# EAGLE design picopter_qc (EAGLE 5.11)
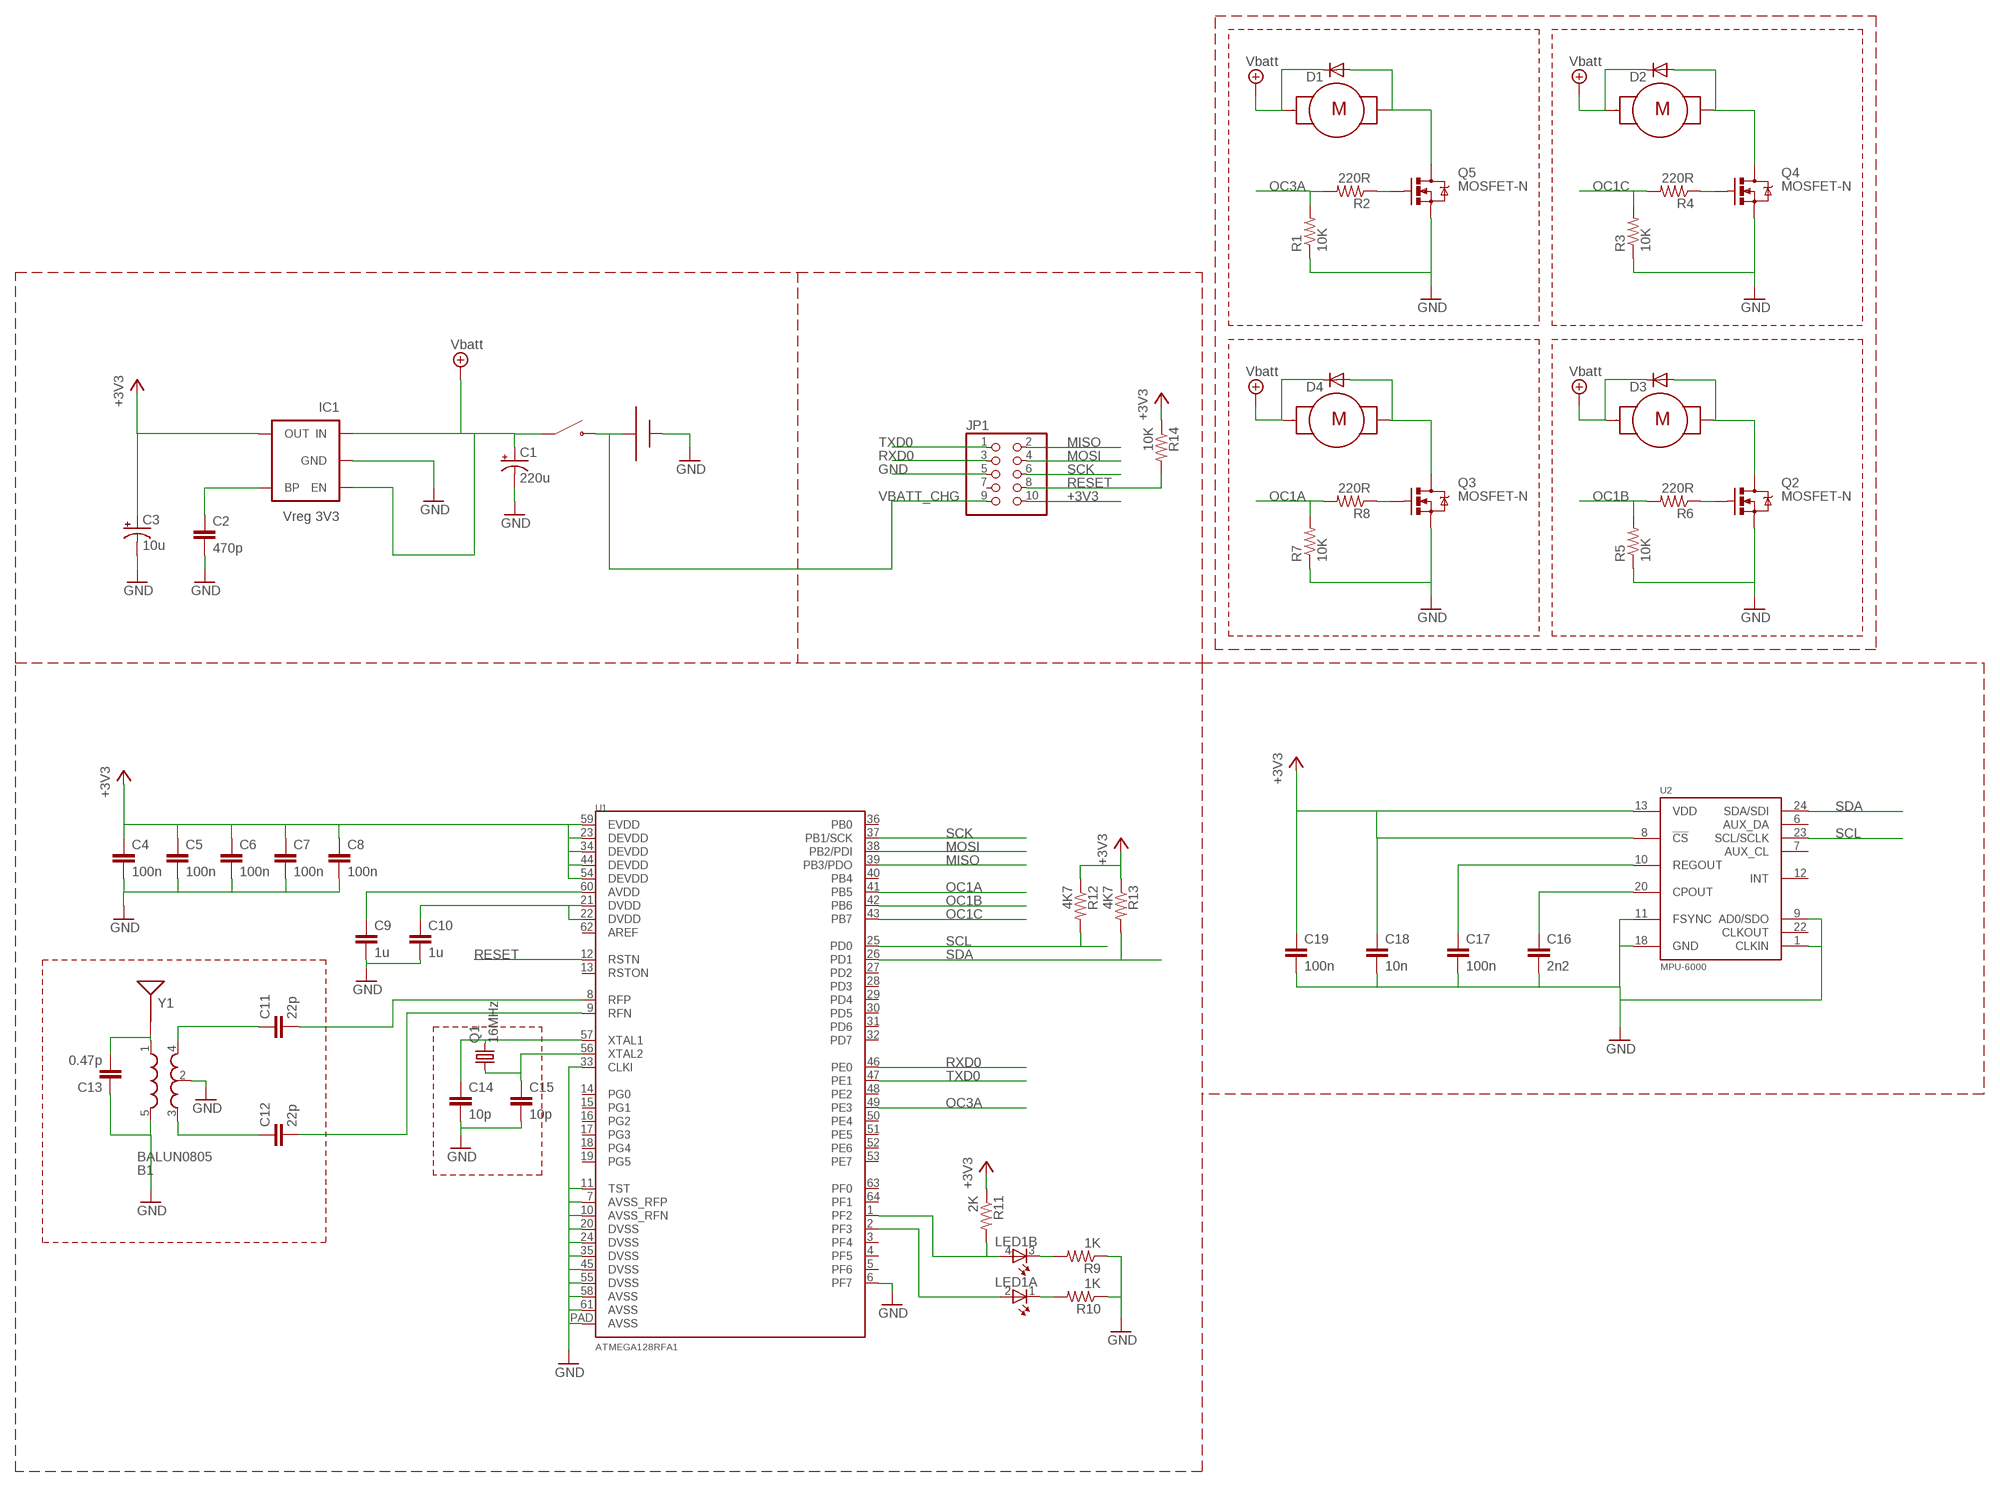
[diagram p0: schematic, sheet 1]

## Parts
B1  BALUN0805  [BALUN]
BATT1  BATT-CONNJST-PH-VERT  [JST-PH-2-VERT]
C1  220u  CPOL-USSMCB  [SMC_B]
C2  470p  C-EUC0603  [C0603]
C3  10u  CPOL-USSMCB  [SMC_B]
C4  100n  C-EUC0603  [C0603]
C5  100n  C-EUC0603  [C0603]
C6  100n  C-EUC0603  [C0603]
C7  100n  C-EUC0603  [C0603]
C8  100n  C-EUC0603  [C0603]
C9  1u  C-EUC0603  [C0603]
C10  1u  C-EUC0603  [C0603]
C11  22p  C-EUC0603  [C0603]
C12  22p  C-EUC0603  [C0603]
C13  0.47p  C-EUC0603  [C0603]
C14  10p  C-EUC0603  [C0603]
C15  10p  C-EUC0603  [C0603]
C16  2n2  C-EUC0603  [C0603]
C17  100n  C-EUC0603  [C0603]
C18  10n  C-EUC0603  [C0603]
C19  100n  C-EUC0603  [C0603]
D1  DIODE-MINIMELF  [MINIMELF]
D2  DIODE-MINIMELF  [MINIMELF]
D3  DIODE-MINIMELF  [MINIMELF]
D4  DIODE-MINIMELF  [MINIMELF]
IC1  Vreg 3V3  V_REG_LDOSMD  [SOT23-5]
JP1  PINHD-2X5EDGE  [2X5-EDGE]
LED1  TOPLED-2-CUSTOM  [TOPLED2CUSTOM]
M1  MOTORARM-CORNER  [MOTOR-CORNER-2]
M2  MOTORARM-CORNER  [MOTOR-CORNER-2]
M3  MOTORARM-CORNER  [MOTOR-CORNER-2]
M4  MOTORARM-CORNER  [MOTOR-CORNER-2]
Q1  16MHz  CRYSTALCTS406  [CTS406]
Q2  MOSFET-N  MOSFET-NCHANNELSMD  [SOT23-3]
Q3  MOSFET-N  MOSFET-NCHANNELSMD  [SOT23-3]
Q4  MOSFET-N  MOSFET-NCHANNELSMD  [SOT23-3]
Q5  MOSFET-N  MOSFET-NCHANNELSMD  [SOT23-3]
R1  10K  R-US_R0603  [R0603]
R2  220R  R-US_R0603  [R0603]
R3  10K  R-US_R0603  [R0603]
R4  220R  R-US_R0603  [R0603]
R5  10K  R-US_R0603  [R0603]
R6  220R  R-US_R0603  [R0603]
R7  10K  R-US_R0603  [R0603]
R8  220R  R-US_R0603  [R0603]
R9  1K  R-US_R0603  [R0603]
R10  1K  R-US_R0603  [R0603]
R11  2K  R-US_R0603  [R0603]
R12  4K7  R-US_R0603  [R0603]
R13  4K7  R-US_R0603  [R0603]
R14  10K  R-US_R0603  [R0603]
S2  SWITCH-PWR-SIMPLE  [SWITCH-PWR]
U1  ATMEGA128RFA1  [QFN-64]
U2  MPU-6000  [QFN-24]
Y1  ANTENNA2SMD5  [ANTENNA-CHIP5]

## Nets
+3V3: C3.+ C4.1 C5.1 C6.1 C7.1 C8.1 C18.1 C19.1 IC1.5(OUT) JP1.10 R11.1 R12.1 R13.1 R14.1 U1.23(DEVDD) U1.34(DEVDD) U1.44(DEVDD) U1.54(DEVDD) U1.59(EVDD) U2.8(!CS) U2.13(VDD)
GND: B1.2(GND) B1.5(GND) BATT1.N C1.- C2.2 C3.- C4.2 C5.2 C6.2 C7.2 C8.2 C9.2 C10.2 C13.1 C14.2 C15.2 C16.2 C17.2 C18.2 C19.2 IC1.2(GND) JP1.5 Q2.2(S) Q3.2(S) Q4.2(S) Q5.2(S) R1.1 R3.1 R5.1 R7.1 R9.1 R10.1 U1.6(PF7) U1.7(AVSS_RFP) U1.10(AVSS_RFN) U1.11(TST) U1.20(DVSS) U1.24(DVSS) U1.33(CLKI) U1.35(DVSS) U1.45(DVSS) U1.55(DVSS) U1.58(AVSS) U1.61(AVSS) U1.PAD(AVSS) U2.1(CLKIN) U2.9(AD0/SDO) U2.11(FSYNC) U2.18(GND)
MISO: JP1.2 U1.39(PB3/PDO)
MOSI: JP1.4 U1.38(PB2/PDI)
MS1: B1.1(IN) C13.2 Y1.FEED(SIGNAL)
N$1: C2.1 IC1.4(BP)
N$2: LED1.4(B:A) R11.2 U1.1(PF2)
N$3: C11.2 U1.8(RFP)
N$4: C10.1 U1.21(DVDD) U1.22(DVDD)
N$5: C9.1 U1.60(AVDD)
N$6: B1.3(OUT1) C12.1
N$7: B1.4(OUT2) C11.1
N$8: C12.2 U1.9(RFN)
N$9: C14.1 Q1.3 U1.57(XTAL1)
N$10: C15.1 Q1.1 U1.56(XTAL2)
N$11: LED1.3(B:C) R9.2
N$12: LED1.1(A:C) R10.2
N$13: LED1.2(A:A) U1.2(PF3)
N$16: C16.1 U2.20(CPOUT)
N$17: C17.1 U2.10(REGOUT)
N$18: D4.A M2.B@1 Q3.3(D)
N$19: D2.A M3.B@1 Q4.3(D)
N$20: D1.A M4.B@1 Q5.3(D)
N$21: D3.A M1.B@1 Q2.3(D)
N$45: Q5.1(G) R2.1
N$46: Q4.1(G) R4.1
N$47: Q2.1(G) R6.1
N$48: Q3.1(G) R8.1
OC1A: R7.2 R8.2 U1.41(PB5)
OC1B: R5.2 R6.2 U1.42(PB6)
OC1C: R3.2 R4.2 U1.43(PB7)
OC3A: R1.2 R2.2 U1.49(PE3)
RESET: JP1.8 R14.2 U1.12(RSTN)
RXD0: JP1.3 U1.46(PE0)
SCK: JP1.6 U1.37(PB1/SCK)
SCL: R12.2 U1.25(PD0) U2.23(SCL/SCLK)
SDA: R13.2 U1.26(PD1) U2.24(SDA/SDI)
TXD0: JP1.1 U1.47(PE1)
VBATT: C1.+ D1.C D2.C D3.C D4.C IC1.1(IN) IC1.3(EN) M1.A@1 M2.A@1 M3.A@1 M4.A@1 S2.P$1 ; supply symbol labelled Vbatt
VBATT_CHG: BATT1.P JP1.9 S2.P$2
Unconnected: JP1.7 U1.3(PF4) U1.4(PF5) U1.5(PF6) U1.13(RSTON) U1.14(PG0) U1.15(PG1) U1.16(PG2) U1.17(PG3) U1.18(PG4) U1.19(PG5) U1.27(PD2) U1.28(PD3) U1.29(PD4) U1.30(PD5) U1.31(PD6) U1.32(PD7) U1.36(PB0) U1.40(PB4) U1.48(PE2) U1.50(PE4) U1.51(PE5) U1.52(PE6) U1.53(PE7) U1.62(AREF) U1.63(PF0) U1.64(PF1) U2.6(AUX_DA) U2.7(AUX_CL) U2.12(INT) U2.22(CLKOUT)

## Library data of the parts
B1 = palmquad_alpha:BALUN
BATT1 = palmquad_alpha:BATT-CONN
C1 C3 = rcl:CPOL-US: POLARIZED CAPACITOR, American symbol
C2 C4-C19 = rcl:C-EU: CAPACITOR, European symbol
D1-D4 = palmquad_alpha:DIODE-: DIODE
IC1 = palmquad_alpha:V_REG_LDO: Voltage Regulator LDO Standard 150mA LDO voltage regulator in SOT-23 layout. Micrel part MIC5205. BP (by-pass) pin is used to lower output noise with 470pF cap.
JP1 = palmquad_alpha:PINHD-2X5: PIN HEADER
LED1 = palmquad_alpha:TOPLED-2-: Multi TOPLED® (two color) LG T672, LP T672 LSY T67B LSW T67C LSY T675 LSY T676 LSG T677 LSG T770 Source: http://www.osram.convergy.de/
M1-M4 = palmquad_alpha:MOTOR
Q1 = palmquad_alpha:CRYSTAL: CRYSTAL; OC_FARNELL: unknown; OC_NEWARK: unknown
Q2-Q5 = palmquad_alpha:MOSFET-NCHANNEL
R1-R14 = rcl:R-US_: RESISTOR, American symbol
S2 = palmquad_alpha:SWITCH-PWR
U1 = palmquad_alpha:ATMEGA128RFA1
U2 = palmquad_alpha:MPU-6000: ITG-3200 3-axis gyro, digital output, qfn24 package
Y1 = palmquad_alpha:ANTENNA2: Antenna

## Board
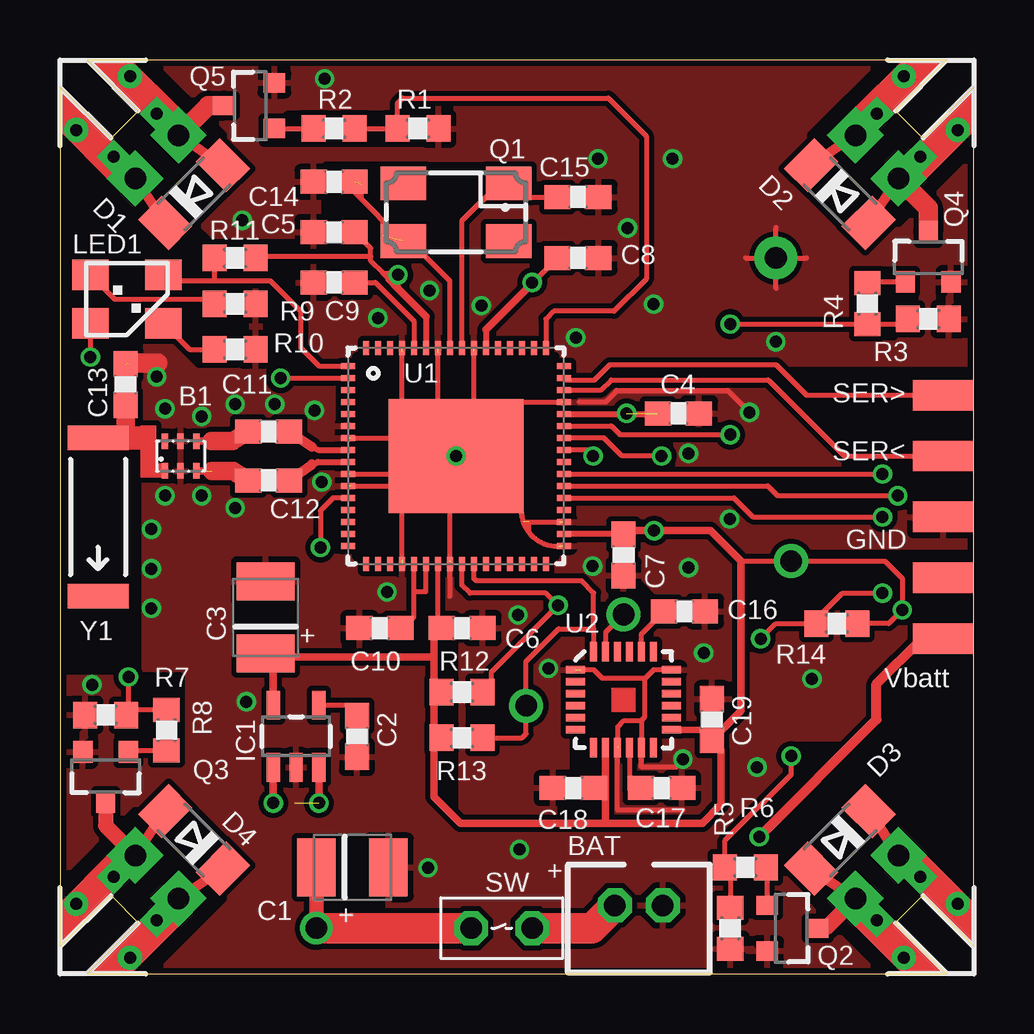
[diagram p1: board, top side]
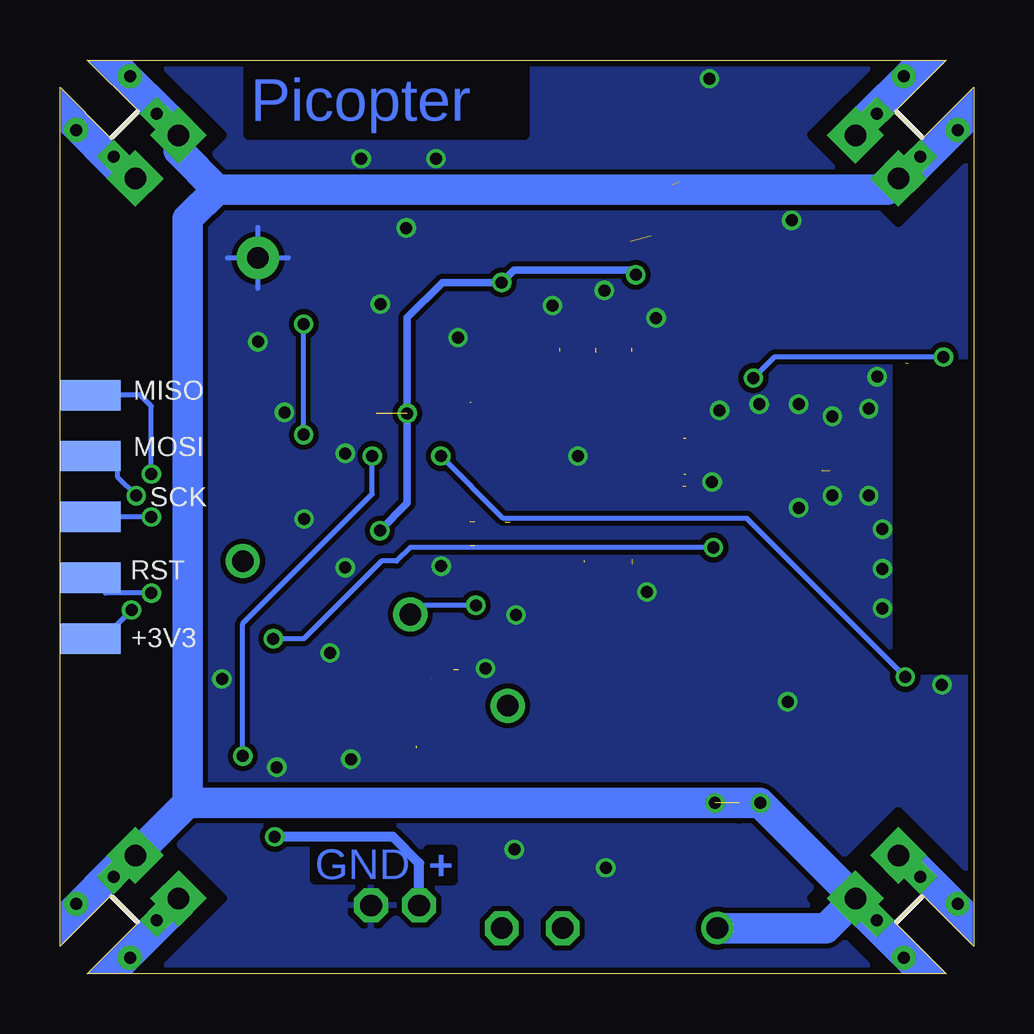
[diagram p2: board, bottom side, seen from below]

Size 38.1 x 38.1 mm. Coordinates in mm from the lower left corner, seen from the top.
Outline: 0,1.14 2.13,3.27 3.27,2.13 1.14,0 36.96,0 34.83,2.13 35.97,3.27 38.1,1.14 38.1,36.96 36.01,34.86 35.94,34.86 34.86,35.94 34.86,36.01 36.96,38.1 1.14,38.1 3.27,35.97 2.13,34.83 0,36.96 0,1.14
Copper layers (1*16): Top 0.035mm / dielectric 1.5mm / Bottom 0.035mm
Design rules "fusion_rules_tentedvias": minimum track width 6mil, minimum drill 0.3mm, track to track 7mil, track to pad 7mil, pad to pad 7mil, via to via 7mil, smd to smd 0mil, copper to edge 10mil, drill to drill 10mil, minimum pad ring 10mil, minimum via ring 6mil, stop-mask expansion 2mil, vias tented up to drill 25mil, thermal gap 10mil
tRestrict: area 0,12.7 to 3.2,25.4; area 12.4,17.4 to 20.6,25.7; area 22,10 to 25,12.9; 52 lines
bRestrict: area 0,12.7 to 3.2,25.4

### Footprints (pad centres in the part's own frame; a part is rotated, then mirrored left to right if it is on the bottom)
BALUN = smd 0.27 x 0.635: 1 -0.7,-0.616; 2 -0.05,-0.616; 3 0.6,-0.616; 4 0.6,0.616; 5 -0.05,0.616; 6 -0.7,0.616
JST-PH-2-VERT = drill 0.9 pad 1.422 octagon: N -1,0; P 1,0
SMC_B = smd 1.6 x 2.4: + -1.5,0; - 1.5,0
C0603 = smd 1.1 x 1: 1 -0.85,0; 2 0.85,0
MINIMELF = smd 1.4 x 1.8: A 1.7,0; C -1.7,0
SOT23-5 = smd 0.55 x 1.2: 1 -0.95,-1.3; 2 0,-1.3; 3 0.95,-1.3; 4 0.95,1.3; 5 -0.95,1.3
2X5-EDGE = smd 2.54 x 1.27: 1 0,5.08; 3 0,2.54; 5 0,0; 7 0,-2.54; 9 0,-5.08 | smd 2.54 x 1.27 bottom: 2 0,5.08; 4 0,2.54; 6 0,0; 8 0,-2.54; 10 0,-5.08
TOPLED2CUSTOM = smd 1.27 x 1.524: 1 -1.016,-1.524; 2 -1.016,1.524; 3 1.016,1.524; 4 1.016,-1.524
MOTOR-CORNER-2 = drill 0.9 pad 1.676 square: A@1 -1.27,-5.715; B@1 1.27,-5.715 | drill 0.5 square: A@2 -1.27,-4.445; B@2 1.27,-4.445 | drill 0.5 round: P$1 -1.587,-2.54; P$2 1.587,-2.54
CTS406 = smd 1.9 x 1.4: 1 -2.2,-1.2; 2 2.2,-1.2; 3 2.2,1.2; 4 -2.2,1.2
SOT23-3 = smd 0.8 x 0.9: 1 -0.95,-1; 2 0.95,-1; 3 0,1.1
R0603 = smd 1 x 1.1: 1 -0.85,0; 2 0.85,0
SWITCH-PWR = drill 0.9 octagon: P$1 -1.27,0; P$2 1.27,0
QFN-64 = smd 0.6 x 0.25: 1 -4.5,3.75; 2 -4.5,3.25; 3 -4.5,2.75; 4 -4.5,2.25; 5 -4.5,1.75; 6 -4.5,1.25; 7 -4.5,0.75; 8 -4.5,0.25; 9 -4.5,-0.25; 10 -4.5,-0.75; 11 -4.5,-1.25; 12 -4.5,-1.75; 13 -4.5,-2.25; 14 -4.5,-2.75; 15 -4.5,-3.25; 16 -4.5,-3.75; 33 4.5,-3.75; 34 4.5,-3.25; 35 4.5,-2.75; 36 4.5,-2.25; 37 4.5,-1.75; 38 4.5,-1.25; 39 4.5,-0.75; 40 4.5,-0.25; 41 4.5,0.25; 42 4.5,0.75; 43 4.5,1.25; 44 4.5,1.75; 45 4.5,2.25; 46 4.5,2.75; 47 4.5,3.25; 48 4.5,3.75 | smd 0.25 x 0.6: 17 -3.75,-4.5; 18 -3.25,-4.5; 19 -2.75,-4.5; 20 -2.25,-4.5; 21 -1.75,-4.5; 22 -1.25,-4.5; 23 -0.75,-4.5; 24 -0.25,-4.5; 25 0.25,-4.5; 26 0.75,-4.5; 27 1.25,-4.5; 28 1.75,-4.5; 29 2.25,-4.5; 30 2.75,-4.5; 31 3.25,-4.5; 32 3.75,-4.5; 49 3.75,4.5; 50 3.25,4.5; 51 2.75,4.5; 52 2.25,4.5; 53 1.75,4.5; 54 1.25,4.5; 55 0.75,4.5; 56 0.25,4.5; 57 -0.25,4.5; 58 -0.75,4.5; 59 -1.25,4.5; 60 -1.75,4.5; 61 -2.25,4.5; 62 -2.75,4.5; 63 -3.25,4.5; 64 -3.75,4.5 | smd 5.639 x 4.75: PAD 0,0
QFN-24 = smd 0.8 x 0.3: 1 -2,1.25; 2 -2,0.75; 3 -2,0.25; 4 -2,-0.25; 5 -2,-0.75; 6 -2,-1.25; 13 2,-1.25; 14 2,-0.75; 15 2,-0.25; 16 2,0.25; 17 2,0.75; 18 2,1.25 | smd 0.3 x 0.8: 7 -1.25,-2; 8 -0.75,-2; 9 -0.25,-2; 10 0.25,-2; 11 0.75,-2; 12 1.25,-2; 19 1.25,2; 20 0.75,2; 21 0.25,2; 22 -0.25,2; 23 -0.75,2; 24 -1.25,2
ANTENNA-CHIP5 = smd 1.016 x 2.54: FEED -3.302,0; NC 3.302,0

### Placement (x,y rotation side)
B1  5.08,21.59 0 top
BATT1  24.13,2.86 180 top
C1  12.19,4.45 0 top
C2  12.38,9.91 270 top
C3  8.57,14.86 90 top
C4  25.78,23.37 0 top
C5  11.43,30.92 180 top
C6  16.76,14.41 0 top
C7  23.5,17.46 270 top
C8  21.59,29.84 0 top
C9  11.43,28.83 180 top
C10  13.34,14.41 180 top
C11  8.7,22.61 0 top
C12  8.7,20.57 0 top
C13  2.73,24.57 270 top
C14  11.43,33.02 180 top
C15  21.59,32.38 0 top
C16  26.04,15.11 0 top
C17  25.08,7.75 0 top
C18  21.4,7.75 180 top
C19  27.18,10.6 90 top
D1  5.59,32.51 45 top
D2  32.51,32.51 315 top
D3  32.51,5.59 225 top
D4  5.59,5.59 135 top
IC1  9.84,9.91 0 top
JP1  36.83,19.05 0 top
LED1  2.79,28.13 90 top
M1  38.1,0 225 top
M2  0,0 135 top
M3  38.1,38.1 315 top
M4  0,38.1 45 top
Q1  16.51,31.75 180 top
Q2  30.48,1.91 270 top
Q3  1.91,8.26 180 top
Q4  36.2,29.84 0 top
Q5  7.94,36.2 90 top
R1  14.92,35.24 180 top
R2  11.43,35.24 0 top
R3  36.2,27.3 180 top
R4  33.66,27.94 270 top
R5  27.94,1.91 90 top
R6  28.57,4.45 180 top
R7  1.91,10.79 0 top
R8  4.45,10.16 90 top
R9  7.3,27.94 180 top
R10  7.3,26.04 180 top
R11  7.3,29.84 180 top
R12  16.76,11.75 0 top
R13  16.76,9.84 0 top
R14  32.38,14.61 180 top
S2  18.41,1.91 0 top
U1  16.51,21.59 0 top
U2  23.5,11.43 0 top
U$1  [PICOPTER-LOGO]  30.16,35.56 0 bottom
U$5  [ARM-MOCK]  35.56,35.56 45 top
U$6  [ARM-MOCK]  2.54,35.56 135 top
U$7  [ARM-MOCK]  2.54,2.54 225 top
U$8  [ARM-MOCK]  35.56,2.54 315 top
Y1  1.59,19.05 270 top

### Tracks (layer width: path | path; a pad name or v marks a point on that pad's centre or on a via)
+3V3  (via drill 0.5, 0.9 pad 1.42)  (1 unrouted)
  Top 0.203: C5.1 12.95,30.25 12.95,29.91 | 12.95,29.91 12.95,29.72 13.46,29.21 | 13.72,28.96 13.46,29.21 | 23.5,18.34 C7.1 23.66,18.48 | U1.23 15.76,14.61 C6.1 | 22.75,7.68 C18.1 | 26.75,10.18 C19.1 27.18,9.34 27.56,9.34 | 24.93,23.34 C4.1 | v19.68,28.83 19.72,28.83 C8.1 | 28.38,17.21 v30.48,17.21 34.39,17.21 35.12,16.48 v35.12,15.18 34.54,14.61 R14.1 | R11.1 8.22,29.91 12.95,29.91 | 13.46,29.21 13.97,29.21 | 15.6,11.81 15.66,11.75 R12.1 | 15.6,9.74 15.6,9.62
  Top 0.254: 17.76,26.86 U1.54 | 15.26,27.41 U1.59 | 23.5,18.34 U1.34 | U1.44 24.93,23.34 | 14.1,28.57 14.1,29.02
  Top 0.279: 26.75,10.18 U2.13 | U2.8 22.75,7.68
  Top 0.305: 19.72,28.83 17.76,26.86 | 15.26,27.41 14.1,28.57 13.72,28.96 13.91,29.15 v14.1,29.15 | 27.56,9.34 27.56,7.06 26.78,6.29 22.75,6.29 | 23.66,18.48 v24.77,18.48 27.11,18.48 28.38,17.21 28.38,10.96 C19.1 | 15.76,14.61 15.6,14.54 15.6,13.21 | 8.89,13.21 8.89,13.36 C3.+ 8.89,13.04 | 8.89,13.21 15.6,13.21 | IC1.5 8.89,10.82 8.89,13.21 | 22.75,6.29 U2.8 | 15.6,13.21 15.6,12 R12.1 | 22.75,6.29 16.69,6.29 15.6,7.38 15.6,9.62 R13.1 | 15.6,11.81 15.6,9.74
  Bottom 0.203: v23.62,23.37 23.59,23.34 | v24.77,18.48 24.83,18.48 | v35.12,15.18 36.32,13.97 JP1.10
  Bottom 0.305: v14.1,29.15 14.29,29.34 19.18,29.34 v19.68,28.83 22.16,28.83 23.62,27.37 v23.62,23.37 23.62,19.62 v24.77,18.48
GND  (via drill 0.5)  (16 unrouted)
  Top 0.203: 14.26,17.27 14.26,19.46 | 16.26,17.23 16.26,19.41 | 18.77,23.84 20.96,23.84 | 17.27,23.77 17.27,25.95 | 15.76,23.72 15.76,25.91 | 14.26,23.75 14.26,25.93 | 12.09,20.84 14.27,20.84 | 12.14,20.34 14.33,20.34 | 12.11,22.34 14.3,22.34 | 20.8,17.83 20.73,17.83 arc-90 19.23,19.33 | 19.33,18.84 20.82,18.84 | 24.24,10.57 24.24,9.58 | 24.24,10.57 24.38,10.71 24.38,12.32 | 24.38,12.32 22.62,12.32 | 23.25,9.5 23.25,10.3 23.52,10.57 24.24,10.57 | 25.3,12.69 24.75,12.69 24.38,12.32 | 21.69,12.68 22.25,12.68 22.61,12.32 | 19.56,18.4 19.56,18.83 | 16.26,15.75 16.26,17.18 | 28.57,29.84 31.11,29.84 | 29.84,28.57 29.84,31.11 | 21.65,23.84 22.73,23.84 23.21,24.32 27.84,24.32 28.73,23.43 | 24.24,9.21 24.24,8.63 25.71,8.63 | U2.9 23.25,6.83 25.98,6.83
  Top 0.813: 2.86,25.46 4.06,25.46
  Bottom 0.203: 28.57,29.84 31.11,29.84 | 29.84,28.57 29.84,31.11
  other vias: 5.91,23.24 4.03,24.89 5.91,19.94 4.38,19.94 4.38,23.56 10.91,20.51 15.41,28.49 17.57,27.86 13.25,27.35 25.97,8.95 7.3,23.75 7.3,19.43 23.66,31.1 29.06,8.62 26.84,13.38 20.36,12.73 1.33,12.06 15.35,4.43 22.2,17 13.63,15.92 26.2,16.94 27.92,18.97 19.09,14.97 28.74,23.41 26.2,21.7 21.51,26.52 3.81,18.54 3.81,16.89 19.16,5.19 7.76,11.35 24.74,27.92 16.51,21.59 8.95,23.75 10.6,23.5 3.81,15.24 25.54,33.99 22.43,33.99 11.03,37.32 7.6,31.41 31.35,12.3 29.84,26.35
  pour Top (isolate 0.216): -0.32,38.42 38.1,38.42 38.1,29.21 38.1,8.89 38.1,-0.32 -0.32,-0.32
  pour Bottom (isolate 0.216): -0.32,38.42 38.1,38.42 38.1,29.21 38.1,8.89 38.1,-0.32 -0.32,-0.32
MISO  (via drill 0.5)
  Top 0.203: U1.39 v34.29,20.84
  Bottom 0.203: v34.29,20.84 34.29,23.67 34.75,24.13 JP1.2
MOSI  (via drill 0.5)
  Top 0.203: U1.38 29.51,20.34 29.91,19.94 v34.92,19.94
  Bottom 0.203: v34.92,19.94 35.69,20.7 35.69,21.02 36.26,21.59 JP1.4
MS1
  Top 0.203: 2.73,22.35 2.98,22.35 3.68,21.65 3.68,20.97 B1.1
  Top 0.762: C13.2 2.73,22.35 Y1.FEED
N$1
  Top 0.203: IC1.4 11.93,11.21 C2.1
N$2
  Top 0.203: U1.1 10.8,25.34 10.03,26.1 10.03,27.62 8.76,28.89 6.45,28.89 | LED1.4 4.32,28.89 6.45,28.89 | 6.45,28.89 R11.2
N$3
  Top 0.254: U1.8 10.75,21.84 10.5,21.97
  Top 0.406: C11.2 10.5,21.97
N$4
  Top 0.203: C10.1 14.76,14.86 14.76,15.94 | 14.76,15.94 U1.21 | U1.22 15.26,15.94 14.76,15.94
N$5
  Top 0.203: C9.1 13.16,28.83 14.76,27.23 U1.60
N$6  (1 unrouted)
  Top 0.305: B1.3 6.01,20.97
  Top 0.762: 6.35,20.95 7.21,20.95 C12.1
N$7
  Top 0.305: B1.4 6.33,22.21
  Top 0.762: 6.33,22.21 7.2,22.21 C11.1
N$8
  Top 0.254: 10.5,21.24 10.75,21.34 U1.9
  Top 0.406: C12.2 10.5,21.24
N$9  (2 unrouted)
  Top 0.203: U1.57 16.26,28.89 14.6,30.55 Q1.3 12.28,32.58 C14.1 | 13.46,30.78 13.46,31.39 | 12.57,32.31 12.57,32.91
N$10
  Top 0.203: U1.56 16.76,31.39 18.32,32.95 Q1.1 arc90 19.27,32.38 C15.1
N$11
  Top 0.203: LED1.3 2.29,28.13 6.45,28.13 R9.2
N$12
  Top 0.203: LED1.1 5.4,26.04 R10.2
N$13  (via drill 0.5)
  Top 0.203: LED1.2 v1.27,25.72 | v9.2,24.84 U1.2
  Bottom 0.203: v1.27,25.72 8.32,25.72 v9.2,24.84
N$14  (via drill 0.9 pad 1.78)
  other vias: 29.84,29.84
N$16
  Top 0.203: U2.20 24.25,14.17 C16.1
N$17
  Top 0.203: U2.10 23.75,7.68 C17.1
N$18
  Top 0.406: M2.B@1 D4.A
  Top 0.635: Q3.3 1.91,6.18 M2.B@1
N$19
  Top 0.406: D2.A M3.B@1
  Top 0.813: M3.B@1 36.2,31.92 Q4.3
N$20
  Top 0.406: M4.B@1 D1.A
  Top 0.813: Q5.3 6.18,36.2 M4.B@1
N$21
  Top 0.406: M1.B@1 D3.A
  Top 0.635: Q2.3 31.92,1.91 M1.B@1
N$45
  Top 0.203: Q5.1 R2.1
N$46
  Top 0.203: R4.1 33.71,28.84 Q4.1
N$47
  Top 0.203: R6.1 arc-90 29.48,4.39 Q2.1
N$48
  Top 0.203: Q3.1 2.91,9.31 R8.1
OC1A  (via drill 0.5)
  Top 0.203: U1.41 21.98,21.84 v22.23,21.59 | v2.86,12.38 2.86,10.9 R7.2 2.97,11.01 R8.2
  Bottom 0.203: v2.86,12.38 9.46,18.99 19.62,18.99 v22.23,21.59
OC1B  (via drill 0.5)
  Top 0.203: U1.42 22.68,22.34 23.43,21.59 v25.08,21.59 | R5.2 27.94,4.23 R6.2 27.73,5.56 30.48,8.32 v30.48,9.08
  Bottom 0.203: v25.08,21.59 25.08,20 30.48,14.61 v30.48,9.08
OC1C  (via drill 0.5)
  Top 0.203: U1.43 22.99,22.84 23.35,22.48 v27.94,22.48 | R3.2 35.13,27.09 R4.2 v27.94,27.09
  Bottom 0.203: v27.94,22.48 v27.94,27.09
OC3A
  Top 0.203: R2.2 R1.2 14.07,36.3 14.29,36.51 22.86,36.51 24.45,34.92 24.45,28.97 23.1,27.62 20.58,27.62 20.26,27.3 U1.49
RESET  (via drill 0.5)
  Top 0.203: U1.12 11.38,19.84 10.86,19.31 v10.86,17.78 | v34.29,15.88 32.62,15.88 31.54,14.79 R14.2 29.84,14.61 v29.21,13.97
  Bottom 0.203: v10.86,17.78 23.5,17.78 24.07,17.21 24.7,17.21 27.94,13.97 v29.21,13.97 | v34.29,15.88 36.2,15.88 JP1.8
RXD0
  Top 0.203: U1.46 22.56,24.34 22.99,24.77 29.53,24.77 32.7,21.59 JP1.3
SCK  (via drill 0.5)
  Top 0.203: U1.37 28.1,19.84 28.89,19.05 v34.29,19.05
  Bottom 0.203: v34.29,19.05 JP1.6
SCL  (via drill 0.5, 0.9 pad 1.42)
  Top 0.203: U1.25 16.76,16.2 17.09,15.88 20.26,15.88 v20.77,15.37 18,12.6 18,11.75 R12.2 | U2.23 22.75,14.24 v23.5,14.99
  Bottom 0.203: v20.77,15.37 23.11,15.37 v23.5,14.99
SDA  (via drill 0.9 pad 1.42)
  Top 0.203: 22.25,14.38 22.25,15.89 21.75,16.38 17.36,16.38 17.26,16.48 U1.26 | 22.25,14.38 U2.24 | 17.36,9.94 R13.2 19.26,9.84 19.43,10.01 v19.43,11.18 19.43,13.03 20.78,14.38 22.25,14.38
TXD0
  Top 0.203: U1.47 21.09,24.77 22.29,24.77 22.92,25.4 29.84,25.4 31.11,24.13 JP1.1
VBATT  (via drill 0.5, 0.9)  (1 unrouted)
  Top 0.305: v8.89,7.13 IC1.1 | v10.79,7.13 IC1.3
  Top 0.406: M2.A@1 D4.C | M1.A@1 D3.C | M3.A@1 D2.C | M4.A@1 D1.C
  Top 0.61: v10.69,1.91 C1.+
  Top 1.27: v10.69,1.91 S2.P$1
  Bottom 0.203: v8.89,7.13 9.54,6.86 9.78,7.13
  Bottom 1.27: 32.77,7.13 M1.A@1 | 32.77,7.13 32.77,31.48 31.55,32.7 | 32.77,7.13 9.78,7.13 8.92,7.13 M2.A@1 6.18,1.91 v10.69,1.91 | M4.A@1 3.6,32.7 31.55,32.7 | M3.A@1 33.16,34.32 31.55,32.7
VBATT_CHG  (via drill 0.5)
  Top 0.406: v29.15,5.71 34.04,10.6 34.04,12.09 35.92,13.97 JP1.9
  Top 1.27: S2.P$2 22.18,1.91 BATT1.P
  Bottom 0.406: v29.15,5.71 24.22,5.71 23.13,4.62 BATT1.P
(copper drawn outside any net)
  shapes: Top area x3

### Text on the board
Bottom: + | GND
_tsilk: SER> | SER< | GND | + | Vbatt | BAT | + | SW | +
_bsilk: MISO | MOSI | SCK | RST | +3V3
